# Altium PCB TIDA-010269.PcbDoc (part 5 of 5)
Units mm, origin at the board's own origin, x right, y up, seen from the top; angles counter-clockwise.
Board outline 87.61 x 53.51 mm, 8 copper layers (Top Layer, GND1, Signal 1, Power 1, Power 2, Signal 2, Layer 1, Bottom Layer), stack 1.645 mm thick; 482 components, 227 nets, 1562 pads, 953 vias.
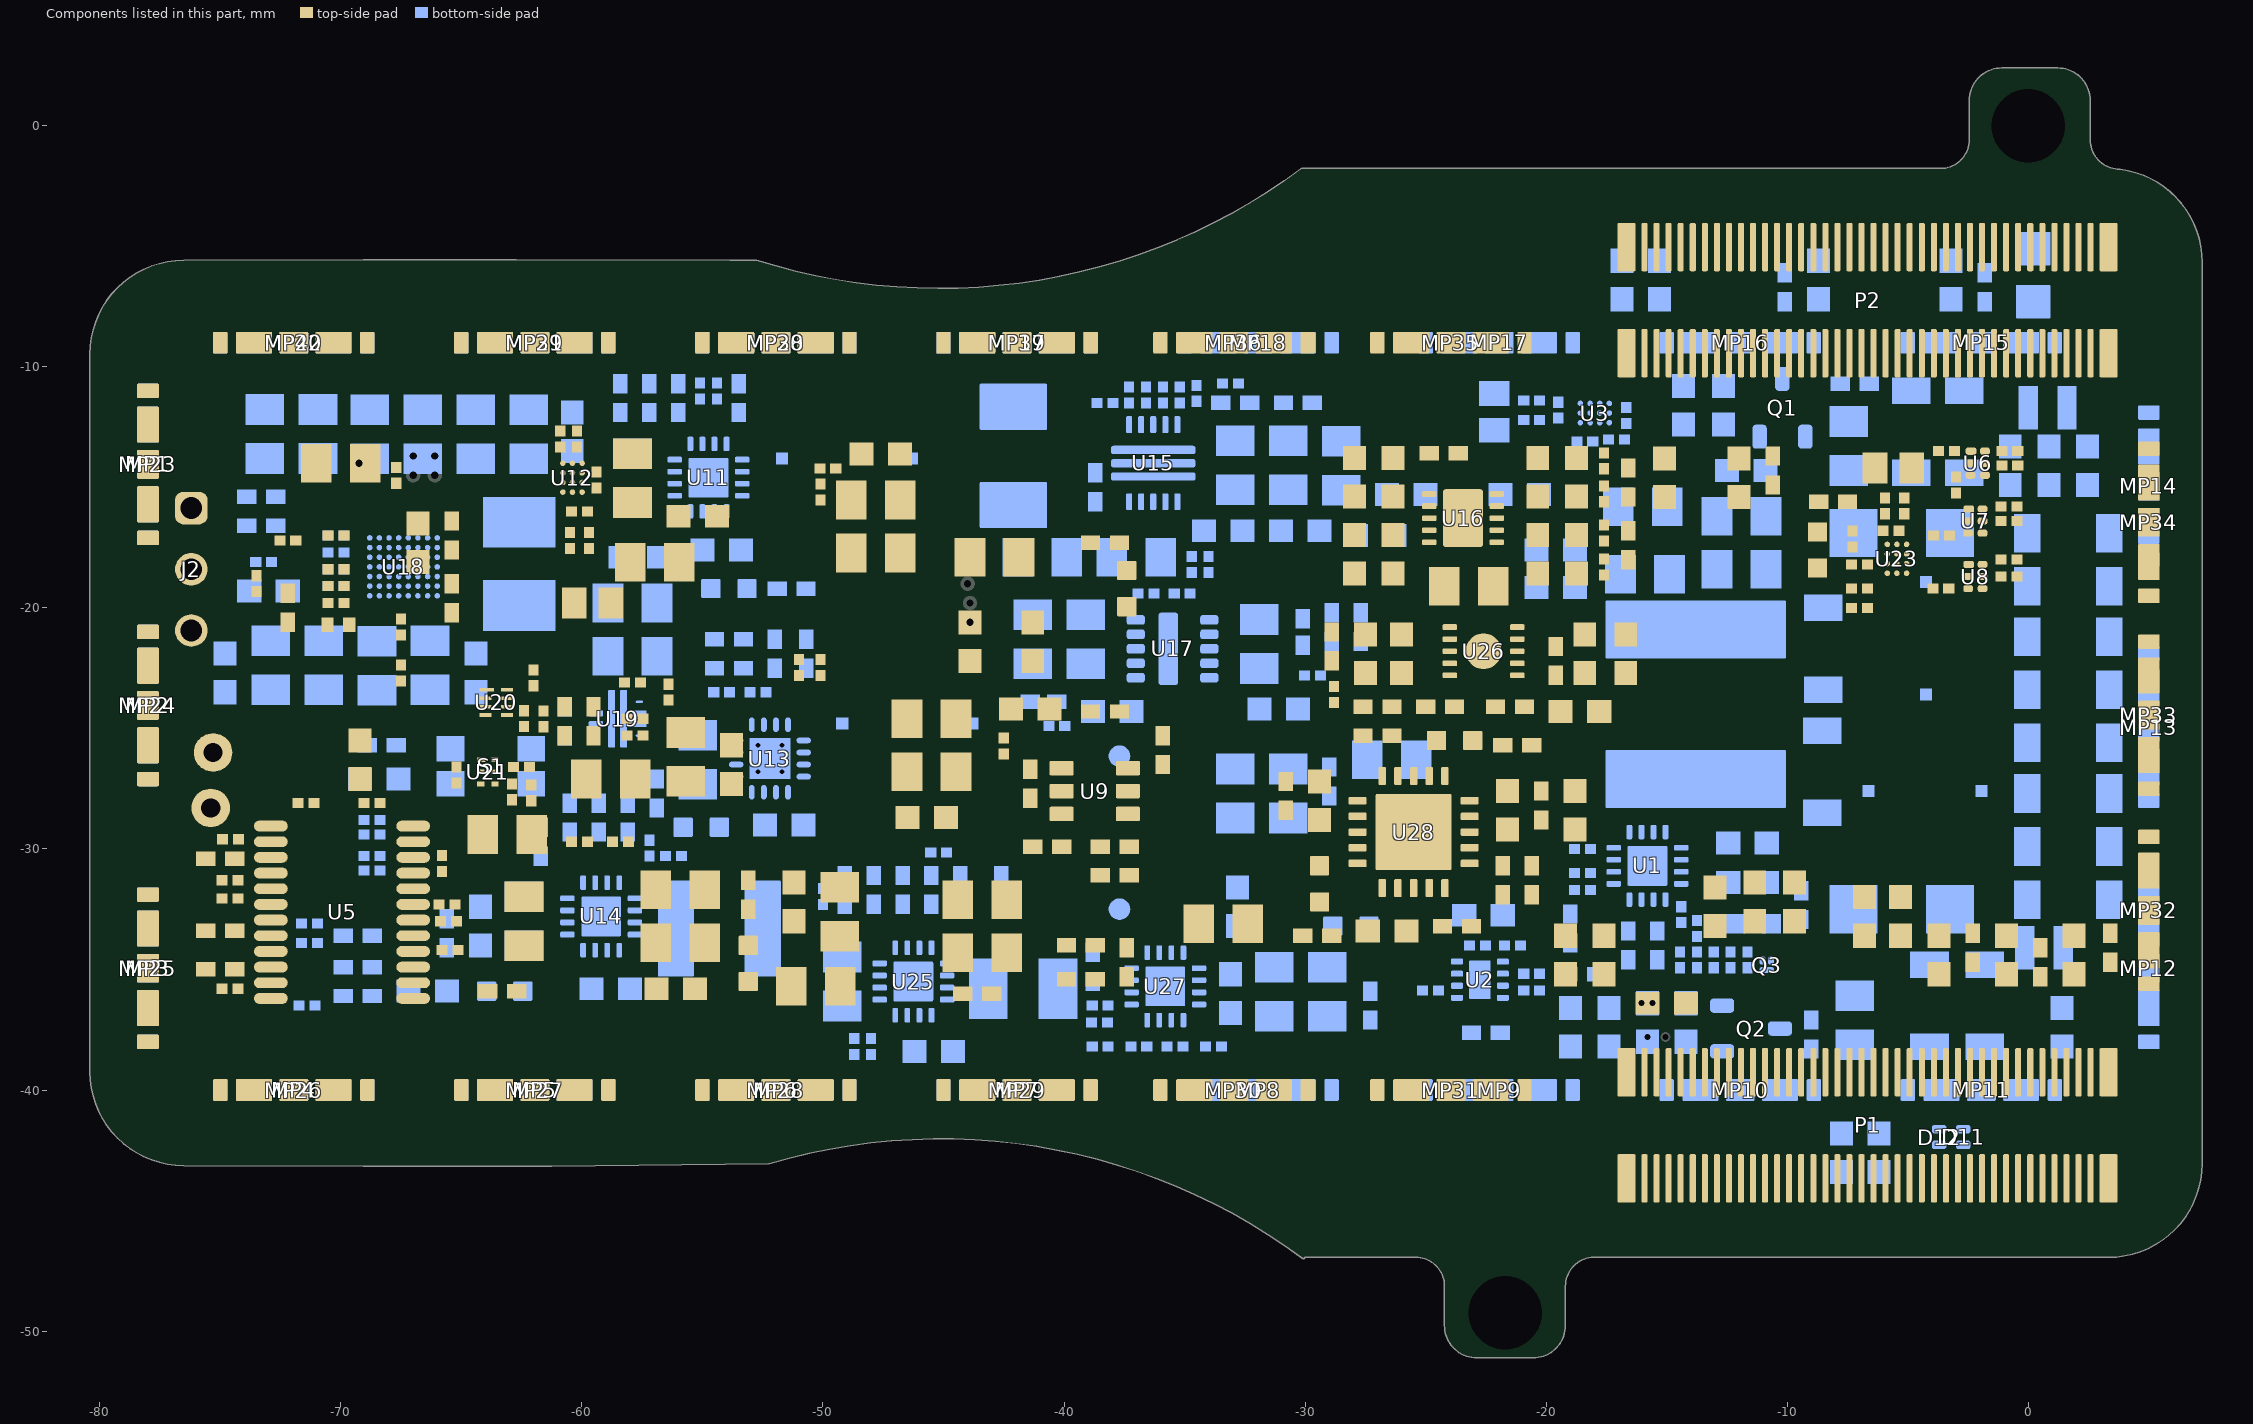
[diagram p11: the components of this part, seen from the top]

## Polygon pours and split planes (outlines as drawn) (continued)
NetC102_1 on Top Layer "TOP_LAYER_NETC102_1_P331" (solid, remove dead copper, pour order 331): -13.475,-32.1 -12.525,-32.1 -12.525,-31.025 -12.4,-30.9 -12.4,-30.5 -12.5,-30.4 -13.35,-30.4 -13.475,-30.525
GND on Top Layer "TOP_LAYER_GND_P292" (solid, remove dead copper, pour order 292): -26.3,-32.925 -26.175,-32.8 -24,-32.8 -23.9,-32.9 -23.9,-33.9 -24.1,-34.1 -26.075,-34.1 -26.3,-33.875
no net on Top Layer "TOP_LAYER_NONET_P284" (solid, remove dead copper, pour order 284): -10.9,-14.5 -9.7,-14.5
MHV on Top Layer "TOP_LAYER_MHV_P282" (solid, remove dead copper, pour order 282): -14.1,-37.3 -14.1,-38 -14.2,-38.1 -16.2,-38.1 -16.31,-38.21 -16.31,-44.63 -16.344,-44.664 -16.997,-44.664 -17.046,-44.615 -17.046,-37.446 -16.8,-37.2 -14.2,-37.2
GND on Top Layer "TOP_LAYER_GND_P276" (solid, remove dead copper, pour order 276): -13.046,-38.314 -13.046,-44.614 -12.996,-44.664 -12.325,-44.664 -12.296,-44.635 -12.296,-38.314 -12.346,-38.264 -12.996,-38.264
GND on Top Layer "TOP_LAYER_GND_P275" (solid, remove dead copper, pour order 275): -15.046,-38.314 -14.996,-38.264 -14.421,-38.264 -14.406,-38.279 -14.31,-38.279 -14.31,-44.599 -14.296,-44.614 -14.346,-44.664 -14.996,-44.664 -15.046,-44.614
GND on Top Layer "TOP_LAYER_GND_P274" (solid, remove dead copper, pour order 274): -9.346,-38.264 -9.296,-38.314 -9.3,-38.318 -9.3,-41 -9.4,-41.1 -10.4,-41.1 -10.5,-41 -10.496,-40.996 -10.496,-38.264 -10.496,-40.996 -10.496,-38.264
GND on Top Layer "TOP_LAYER_GND_P273" (solid, remove dead copper, pour order 273): -10.546,-44.635 -10.516,-44.664 -9.421,-44.664 -9.296,-44.539 -9.296,-42.504 -9.3,-42.5 -9.3,-42.3 -9.5,-42.1 -10.4,-42.1 -10.546,-42.246
PHV on Top Layer "TOP_LAYER_PHV_P267" (solid, remove dead copper, pour order 267): -16.997,-4.038 -16.344,-4.038 -16.296,-4.086 -16.296,-10.504 -16.2,-10.6 -15.1,-10.6 -15,-10.7 -15,-11.8 -15.1,-11.9 -16.3,-11.9 -16.9,-11.9 -17.046,-11.754 -17.046,-4.086
NetC112_1 on Top Layer "TOP_LAYER_NETC112_1_P189" (solid, remove dead copper, pour order 189): 20 vertices, not listed, extent -22.8,-18 -16.3,-16.34
NetC169_1 on Top Layer "TOP_LAYER_NETC169_1_P256" (solid, remove dead copper, pour order 256): -18.875,-20.6 -14.2,-20.6 -14.2,-24.1 -15.9,-24.1 -15.9,-21.6 -18.875,-21.6
NetC169_1 on Top Layer "TOP_LAYER_NETC169_1_P248" (solid, remove dead copper, pour order 248): -21.45,-21.9 -20,-21.9 -19.9,-22 -19.3,-22 -19.3,-21.6 -14.6,-21.6 -14.625,-21.575 -14.625,-14.9 -15.575,-14.9 -15.7,-15.025 -15.7,-20.6 -21.37,-20.6 -21.485,-20.716 -21.485,-21.905
NetC112_1 on Top Layer "TOP_LAYER_NETC112_1_P245" (solid, remove dead copper, pour order 245): -18.725,-34.1 -20,-34.1 -20,-33.1 -21,-33.1 -21,-32.5 -18.7,-32.5 -18.7,-34.075
NetC63_1 on Top Layer "TOP_LAYER_NETC63_1_P238" (solid, remove dead copper, pour order 238): -47.435,-14.725 -47.41,-14.7 -45.8,-14.7 -45.8,-22.9 -45.9,-23 -47.5,-23 -47.5,-14.79 -47.435,-14.725
VDD_FPGA on Top Layer "TOP_LAYER_VDD_FPGA_P235" (solid, remove dead copper, pour order 235): 26 vertices, not listed, extent -60.317,-29.3 -48.2,-17.3
VDD_FPGA on Top Layer "TOP_LAYER_VDD_FPGA_P233" (solid, remove dead copper, pour order 233): -60.8,-20.4 -59.8,-20.4 -59.7,-20.3 -59.7,-18.887 -57.413,-18.887 -57.4,-18.9 -57.4,-17.3 -58.6,-17.3 -58.7,-17.4 -58.7,-18 -60.8,-18
NetC135_1 on Top Layer "TOP_LAYER_NETC135_1_P221" (solid, remove dead copper, pour order 221): 18 vertices, not listed, extent -67.4,-24 -58,-13.2
GND on Top Layer "TOP_LAYER_GND_P212" (solid, remove dead copper, pour order 212): 18 vertices, not listed, extent -21.5,-24.775 -16.225,-22.2
NetC172_1 on Top Layer "TOP_LAYER_NETC172_1_P204" (solid, remove dead copper, pour order 204): -43.019,-31.3 -41.749,-31.3 -41.749,-33.872 -41.721,-33.9 -41,-33.9 -41,-36.3 -43.4,-36.3 -43.4,-35.7 -43,-35.7 -43.019,-35.681
NetC81_1 on Top Layer "TOP_LAYER_NETC81_1_P124" (solid, remove dead copper, pour order 124): -55.619,-30.9 -53.725,-30.9 -53.675,-36.3 -54.5,-36.3 -54.525,-36.275 -55.8,-36.275 -55.8,-35.325 -55.619,-35.325
NetC125_1 on Top Layer "TOP_LAYER_NETC125_1_P170" (solid, remove dead copper, pour order 170): -70.381,-14.8 -74,-14.8 -74,-20.1 -72.7,-20.1 -72.7,-22.4 -75.2,-22.4 -75.2,-13.2 -70.381,-13.2 -70.381,-13.433
VDD_FPGA on Top Layer "TOP_LAYER_VDD_FPGA_P201" (solid, remove dead copper, pour order 201): -62.719,-28.6 -60.451,-28.6 -60.451,-26.3 -59.181,-26.3 -59.181,-29.3 -61.449,-29.3 -61.449,-30.2 -62.719,-30.2
NetC102_1 on Top Layer "TOP_LAYER_NETC102_1_P193" (solid, remove dead copper, pour order 193): 17 vertices, not listed, extent -22.3,-15.88 -16.3,-14.88
NetC113_1 on Top Layer "TOP_LAYER_NETC113_1_P181" (solid, remove dead copper, pour order 181): -28.425,-16.48 -25.875,-16.48 -25.875,-17.16 -24.601,-17.16 -24.601,-17.48 -25.875,-17.48 -28.425,-17.48
GND on Top Layer "TOP_LAYER_GND_P180" (solid, remove dead copper, pour order 180): -25.875,-14.28 -29.7,-14.28 -29.7,-12.4 -27.3,-12.4 -27.3,-13.3 -27.28,-13.28 -25.875,-13.28
GND on Top Layer "TOP_LAYER_GND_P046" (solid, remove dead copper, pour order 46): 20 vertices, not listed, extent -51.675,-36.3 -43.781,-30.7
NetC75_1 on Top Layer "TOP_LAYER_NETC75_1_P173" (solid, remove dead copper, pour order 173): -63.481,-28.6 -63.481,-33 -61.6,-33 -61.6,-36.2 -63.1,-36.2 -63.1,-35.1 -63.6,-34.6 -64.7,-34.6 -64.7,-28.6
GND on Top Layer "TOP_LAYER_GND_P061" (solid, remove dead copper, pour order 61): -53.3,-16.7 -54.875,-16.7 -54.9,-16.675 -54.9,-15.4 -55.6,-15.4 -55.6,-14.616 -59.61,-14.616 -59.61,-14.37 -59.61,-12.9 -53.3,-12.9
NetC195_1 on Top Layer "TOP_LAYER_NETC195_1_P048" (solid, remove dead copper, pour order 48): -28.185,-29.44 -27.4,-29.44 -27.4,-27.4 -26.645,-27.337 -26.645,-26 -31.8,-26 -31.8,-27.673 -31.7,-27.673 -28.322,-27.673 -28.15,-27.845 -28.185,-27.88
NetC206_1 on Top Layer "TOP_LAYER_NETC206_1_P165" (solid, remove dead copper, pour order 165): -39.1,-35.1 -39.1,-35.7 -37.1,-35.7 -37.1,-34.8 -39.1,-34.8
NetC122_2 on Top Layer "TOP_LAYER_NETC122_2_P135" (solid, remove dead copper, pour order 135): -35.975,-20.2 -34.25,-20.2 -34.2,-20.25 -34.2,-22.05 -34.2,-21.8 -30.5,-21.8 -30.5,-21.15 -29.8,-21.15 -29.8,-21.95 -29.8,-23 -36.075,-23 -36.075,-20.3
VDDM_LV5 on Top Layer "TOP_LAYER_VDDM_LV5_P160" (solid, remove dead copper, pour order 160): -19.675,-34.7 -17.3,-34.7 -17.3,-44.9 -14.046,-44.9 -14.046,-42.714 -13.296,-42.714 -13.2,-42.81 -13.2,-45.8 -18.3,-45.8 -18.3,-36 -19.7,-36 -19.675,-35.975
VDDP_LV5 on Top Layer "TOP_LAYER_VDDP_LV5_P158" (solid, remove dead copper, pour order 158): -10.8,-32.7 -10.8,-37.9 -10.8,-44.6 -12,-44.6 -12,-35.3 -13.6,-35.3 -13.6,-32.7
VCC_INT_1V on Top Layer "TOP_LAYER_VCC_INT_1V_P150" (solid, remove dead copper, pour order 150): -2.6,-34.3 -2,-34.3 -2,-36 -4.796,-36 -4.796,-44.614 -4.846,-44.664 -4.86,-44.649 -5.531,-44.649 -5.531,-34.7 -4.175,-34.7 -2.6,-34.7
VCC_AUX_1V8 on Top Layer "TOP_LAYER_VCC_AUX_1V8_P148" (solid, remove dead copper, pour order 148): 18 vertices, not listed, extent -2.046,-40.264 0.8,-34.7
NetC169_1 on Top Layer "TOP_LAYER_NETC169_1_P144" (solid, remove dead copper, pour order 144): -22.835,-18.3 -21,-18.3 -21,-20 -20,-20 -20,-21.8 -20.1,-21.9 -21.45,-21.9 -21.45,-20.15 -21.565,-20.035 -21.565,-19.9 -22.835,-19.9
NetC172_1 on Top Layer "TOP_LAYER_NETC172_1_P143" (solid, remove dead copper, pour order 143): -24.867,-18.3 -24.9,-18.333 -24.9,-21.4 -23.772,-21.4 -23.751,-21.421 -23.597,-21.267 -23.597,-18.3
GND on Top Layer "TOP_LAYER_GND_P142" (solid, remove dead copper, pour order 142): 19 vertices, not listed, extent -25.1,-17.48 -18.275,-13.1
VBUS on Top Layer "TOP_LAYER_VBUS_P140" (solid, remove dead copper, pour order 140): -44.535,-17.1 -44.535,-20.94 -44.375,-21.1 -43.425,-21.1 -43.425,-18.86 -43.265,-18.7 -43.265,-17.1
NetC120_1 on Top Layer "TOP_LAYER_NETC120_1_P139" (solid, remove dead copper, pour order 139): -44.375,-21.7 -40.825,-21.7 -40.825,-23 -44.3,-23 -44.4,-22.9 -44.375,-22.875
NetC72_1 on Top Layer "TOP_LAYER_NETC72_1_P138" (solid, remove dead copper, pour order 138): -58.419,-26.3 -58.419,-27.9 -56.565,-27.9 -56.465,-27.8 -53.325,-27.8 -53.325,-26.8 -54.9,-26.8 -54.9,-26.565 -56.5,-26.565 -56.505,-26.57 -57.149,-26.57 -57.149,-26.3
GND on Top Layer "TOP_LAYER_GND_P127" (solid, remove dead copper, pour order 127): -40.749,-27.5 -40.6,-27.351 -39.6,-27.351 -39.6,-27.87 -39.63,-27.9 -41.1,-27.9 -41.1,-28.3 -42.3,-28.3 -42.3,-27.5 -41.1,-27.5
GND on Top Layer "TOP_LAYER_GND_P126" (solid, remove dead copper, pour order 126): -41.1,-27.5 -41.1,-29.6 -40.9,-29.6 -40.9,-30.4 -42.2,-30.4 -42.2,-31.5 -44.6,-31.5 -44.6,-30.7 -43,-30.7 -43,-27.5
NetC174_1 on Top Layer "TOP_LAYER_NETC174_1_P123" (solid, remove dead copper, pour order 123): 23 vertices, not listed, extent -53.4,-36.8 -48.5,-30.9
GND on Top Layer "TOP_LAYER_GND_P122" (solid, remove dead copper, pour order 122): -57.651,-30.9 -56.381,-30.9 -56.381,-34.7 -56.599,-34.7 -56.599,-36.274 -56.6,-36.275 -57.6,-36.275 -57.6,-33.696 -57.651,-33.645 -57.706,-33.7 -60,-33.7 -60,-32 -57.673,-32 -57.651,-31.978
GND on Top Layer "TOP_LAYER_GND_P075" (solid, remove dead copper, pour order 75): -62.87,-24.7 -59.219,-24.7 -59.219,-26.16 -61.76,-26.16 -61.75,-26.17 -61.75,-27.57 -62.87,-27.57 -62.87,-26.5
GND on Top Layer "TOP_LAYER_GND_P101" (solid, remove dead copper, pour order 101): 19 vertices, not listed, extent -29.01,-25.6 -25.721,-22.2
NetC109_1 on Top Layer "TOP_LAYER_NETC109_1_P099" (solid, remove dead copper, pour order 99): -28.425,-14.88 -28.405,-14.9 -24.6,-14.9 -24.6,-15.899 -24.601,-15.9 -24.621,-15.88 -28.425,-15.88
GND on Top Layer "TOP_LAYER_GND_P097" (solid, remove dead copper, pour order 97): -47.151,-23.8 -45.881,-23.8 -45.881,-27.981 -46,-28.1 -46,-29.175 -47,-29.175 -47,-27.751 -47.151,-27.6
GND on Top Layer "TOP_LAYER_GND_P095" (solid, remove dead copper, pour order 95): -56.67,-25.803 -54.403,-25.803 -54.275,-25.931 -54.275,-26.2 -53.325,-26.2 -53,-26.2 -53,-27.1 -51.3,-27.1 -51.3,-25 -54,-25 -54,-23.6 -56.67,-23.6
NetC63_1 on Top Layer "TOP_LAYER_NETC63_1_P063" (solid, remove dead copper, pour order 63): -47.3,-13.15 -47.3,-14.59 -47.435,-14.725 -47.435,-18.525 -45.9,-18.525 -45.9,-14.925 -45.9,-13.15
NetC172_1 on Top Layer "TOP_LAYER_NETC172_1_P032" (solid, remove dead copper, pour order 32): -29.2,-20.6 -24.38,-20.6 -24.285,-20.695 -24.27,-20.68 -23.75,-20.68 -23.75,-21.42 -23.751,-21.421 -25.525,-21.421 -25.525,-21.6 -27.975,-21.6 -27.975,-21.41 -27.985,-21.4 -29.2,-21.4
NetC190_1 on Top Layer "TOP_LAYER_NETC190_1_P031" (solid, remove dead copper, pour order 31): 18 vertices, not listed, extent -24.305,-29.455 -18.325,-26.3
NetC79_1 on Power 2 "POWER_2_NETC79_1_P365" (solid, remove dead copper, pour order 365): -3.25,-31.3 -6.3,-31.3 -6.5,-31.1 -6.5,-27.75 -6.75,-27.5 -54.604,-27.5 -56,-26.105 -56,-22 -54.5,-20.5 -2.9,-20.5 -2.4,-21 -2.4,-30.45
VCC_AUX_1V8 on Power 2 "POWER_2_VCC_AUX_1V8_P304" (solid, remove dead copper, pour order 304): -58,-22.346 -55.654,-20 -16,-20 -16,-10 -18,-8 -78,-8 -80,-10 -80,-39.653 -77.653,-42 -58,-42
VCC_AUX_1V8 on Power 2 "POWER_2_VCC_AUX_1V8_P310" (solid, remove dead copper, pour order 310): -3,-35.5 -0.1,-35.5 0.4,-35 0.4,-21 -0.6,-20 -19,-20 -19,-8.844 -18.156,-8 4,-8 6,-10 6,-42 4,-44 -3.1,-44 -3.1,-35.6
NetC81_1 on Power 2 "POWER_2_NETC81_1_P309" (solid, remove dead copper, pour order 309): -10.05,-27.9 -5.95,-32 -0.5,-32 -0.2,-32.3 -0.2,-34.4 -1,-35.2 -54.678,-35.2 -56,-33.878 -56,-29 -54.9,-27.9
VCC_AUX_1V8 on Power 2 "POWER_2_VCC_AUX_1V8_P305" (solid, remove dead copper, pour order 305): -29,-43 -28,-44 -2,-44 -1,-43 -1,-36 -1.5,-35.5 -27.5,-35.5 -29,-37
VBUS_HV on Power 1 "POWER_1_VBUS_HV_P316" (solid, remove dead copper, pour order 316): -23.6,-14.1 -23.6,-18.4 -22.3,-19.7 -15.7,-19.7 -15,-19 -15,-12.9 -15.9,-12 -23.1,-12 -23.6,-12.5
VCCO_2V5 on Power 1 "POWER_1_VCCO_2V5_P401" (solid, remove dead copper, pour order 401): 18 vertices, not listed, extent -69.95,-41 -19.8,-26
1V8_DVDD on Power 1 "POWER_1_1V8_DVDD_P394" (solid, remove dead copper, pour order 394): 22 vertices, not listed, extent -17.927,-44.65 6,-13
NetC125_1 on Power 1 "POWER_1_NETC125_1_P324" (solid, remove dead copper, pour order 324): 17 vertices, not listed, extent -77,-25 1.219,-7.35
VBUS on Power 1 "POWER_1_VBUS_P318" (solid, remove dead copper, pour order 318): 22 vertices, not listed, extent -60,-37 -24,-12
VDD on Power 1 "POWER_1_VDD_P325" (solid, remove dead copper, pour order 325): -67.91,-27.85 -67.5,-28.223 -67.5,-36.4 -67.85,-36.75 -71.5,-36.75 -72.55,-35.7 -72.55,-28.85 -71.55,-27.85
NetC63_1 on Power 1 "POWER_1_NETC63_1_P323" (solid, remove dead copper, pour order 323): -27,-31 -26.3,-31.7 -2.684,-31.7 -2,-31.016 -2,-20.8 -2.4,-20.4 -25.9,-20.4 -27,-21.5
NetC63_1 on Power 1 "POWER_1_NETC63_1_P322" (solid, remove dead copper, pour order 322): -48,-23.8 -47.8,-24 -18.4,-24 -3.8,-24 -2,-22.2 -2,-20.8 -2.4,-20.4 -41.3,-20.4 -42.2,-21.3 -47.8,-21.3 -48,-21.5
VBUS on Power 1 "POWER_1_VBUS_P321" (solid, remove dead copper, pour order 321): -43,-20.8 -43.2,-21 -44.8,-21 -45,-20.8 -45,-18.8 -45.819,-17.981 -45.819,-13 -42.3,-13 -42.3,-18.1 -43,-18.8
GND on Signal 2 "SIGNAL_2_GND_P431" (solid, remove dead copper, pour order 431): -75.707,-46.943 -80.4,-42.25 -80.4,-3.15 -79,-1.75 4.95,-1.75 7.206,-4.006 7.206,-46.144 6.407,-46.943 3.574,-46.943
AVDD_1P2 on Signal 2 "SIGNAL_2_AVDD_1P2_P422" (solid, remove dead copper, pour order 422): -6.25,-5.8 -5.9,-6.15 -5.9,-11.05 -6.15,-11.3 -8.6,-11.3 -8.95,-11.65 -8.95,-13.1 -9.75,-13.9 -12.2,-13.9 -12.7,-13.4 -12.7,-6.05 -12.45,-5.8
VBUS on Signal 2 "SIGNAL_2_VBUS_P330" (solid, remove dead copper, pour order 330): -19.202,-11.502 -19.202,-12.998 -18.9,-13.3 -17.2,-13.3 -17.2,-16.8 -16.7,-17.3 -16.7,-24.5 -16.55,-24.65 -15.5,-24.65 -15.3,-24.45 -15.3,-11 -15.5,-10.8 -18.5,-10.8
NetC102_1 on Signal 2 "SIGNAL_2_NETC102_1_P423" (solid, remove dead copper, pour order 423): 26 vertices, not listed, extent -22.5,-30.9 -11.375,-7.85
USB_5V on Signal 2 "SIGNAL_2_USB_5V_P419" (solid, remove dead copper, pour order 419): -3.5,-5.8 -5.45,-5.8 -5.7,-6.05 -5.7,-11.45 -6.1,-11.85 -7.1,-11.85 -7.6,-12.35 -7.6,-14.55 -7.15,-15 -6,-15 -3.95,-15 -3.2,-14.25 -3.2,-6.1
NetC112_1 on Signal 2 "SIGNAL_2_NETC112_1_P328" (solid, remove dead copper, pour order 328): -24.3,-17.2 -17.7,-17.2 -17,-17.9 -17,-27 -18,-28 -18,-33.2 -18.4,-33.6 -23.9,-33.6 -25,-32.5 -25,-17.9
GND on Signal 1 "SIGNAL_1_GND_P430" (solid, remove dead copper, pour order 430): -3.297,-1.723 -77.623,-1.723 -80.5,-4.6 -80.374,-4.726 -80.374,-44.876 -78.15,-47.1 -77.993,-46.943 6.507,-46.943 7.25,-46.2 7.25,-2 7.45,-1.8 7.424,-1.774 -3.644,-1.774
VBUS on Signal 1 "SIGNAL_1_VBUS_P369" (solid, remove dead copper, pour order 369): -16.7,-21.8 -16.7,-24.4 -16.55,-24.55 -1.1,-24.55 -0.5,-23.95 -0.5,-14.1 -0.8,-13.8 -2.45,-13.8 -2.75,-14.1 -2.75,-16.9 -6.85,-21 -15.9,-21
VCCO_2V5 on Signal 1 "SIGNAL_1_VCCO_2V5_P402" (solid, remove dead copper, pour order 402): -8.3,-37.8 -8,-38.1 -8,-41.6 -8.15,-41.75 -22.25,-41.75 -23.1,-40.9 -23.1,-38.25 -22.65,-37.8 -22.25,-37.8
GND on GND1 "GND1_GND_P383" (solid, remove dead copper, pour order 383): 4.325,-46.81 3.936,-47.2 -78.25,-47.2 -80.3,-45.15 -80.3,-3.8 -78.25,-1.75 -78.1,-1.9 4.15,-1.9 7.4,-5.15 7.074,-5.476 7.074,-45.176 5.44,-46.81
GND on Layer 1 "LAYER_1_GND_P467" (solid, remove dead copper, pour order 467): -30.188,-1.796 4.896,-1.796 7.074,-3.974 7.074,-44.063 4.271,-46.866 -76.034,-46.866 -80.33,-42.57 -80.33,-6.33 -79,-5 -36.4,-5 -33.185,-1.785 -30.161,-1.785
HVGND on Layer 1 "LAYER_1_HVGND_P466" (solid, remove dead copper, pour order 466): -28.2,-8 -25.784,-5.584 1.784,-5.584 3.981,-7.781 3.981,-41.919 2.488,-43.412 -25.788,-43.412 -28.2,-41

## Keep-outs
Keep-Out Layer:
  circle w0.003: c-75.898,-44.595 r1.331
  circle w0.003: c-75.898,-4.107 r1.331

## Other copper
Signal 2:
  text ".layer_name" at -77.79,-98.031 h1.85
Bottom Layer:
  pour cut-out: -15.2,-28.7 -15,-28.5

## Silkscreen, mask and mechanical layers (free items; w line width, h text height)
Top Overlay:
  text "TIDA-010269" at -30,-5 h1.02
  text "REV 00" at -29.9,-6.3 h1.02
  text "C" at -17.1,-49 h1.02
Bottom Overlay:
  text ".Layer_Name" at -80.711,-98.21 h1.52
Top Paste:
  text ".Layer_Name" at -80.711,-98.21 h1.52
Bottom Paste:
  text ".Layer_Name" at -80.711,-98.21 h1.52
Top Solder:
  text ".Layer_Name" at -80.711,-98.21 h1.52
  text ".Layer_Name" at -80.711,-98.21 h1.52
Bottom Solder:
  text ".Layer_Name" at -80.711,-98.21 h1.52
Drill Guide:
  text ".Layer_Name" at -80.711,-98.21 h1.52
M1 Board Outline:
  lines w0.152: -80.33,-27 -80.33,-9.471 cw(c-76.52,-9.471) -76.52,-5.661 -69.07,-5.628 -62.72,-5.628 -53.873,-5.649 -52.783,-5.649 ccw(c-45.171,18.387) -30.143,-1.857 ; -80.33,-19.634 -80.33,-39.246 ccw(c-76.52,-39.246) -76.52,-43.056 -69.07,-43.085 -61.266,-43.085 ; -61.45,-43.085 -52.256,-43.085 ; -52.574,-43.082 cw(c-45.102,-67.162) -30.074,-46.917 ; -30.134,-1.851 -3.644,-1.851 ccw(c-3.644,-0.581) -2.374,-0.581 -2.374,1.05 cw(c-1.104,1.05) -1.104,2.32 1.219,2.32 cw(c1.219,1.05) 2.489,1.05 2.489,-0.581 ccw(c3.79,-0.581) 3.804,-1.882 cw(c3.32,-5.661) 7.13,-5.661 7.13,-43.056 cw(c3.32,-43.056) 3.32,-46.866 -17.922,-46.866 ccw(c-18.006,-48.136) -19.279,-48.136 -19.279,-49.767 cw(c-20.549,-49.767) -20.549,-51.037 -22.872,-51.037 cw(c-22.872,-49.767) -24.142,-49.767 -24.142,-48.136 ccw(c-25.412,-48.136) -25.412,-46.866 -30.127,-46.866 -30.131,-46.87
M2 Board Dimensions:
  rectangle: -95.367,-83.39 -92.192,-80.215
  rectangle: -92.192,-86.565 -82.667,-83.39
  lines w0.178: -95.367,-83.39 -69.967,-83.39 ; -92.192,-86.565 -92.192,-80.215 ; -89.017,-86.565 -89.017,-80.215 ; -82.667,-86.565 -82.667,-80.215 ; -76.317,-86.565 -76.317,-80.215 ; -95.367,-86.565 -69.967,-86.565 -69.967,-80.215 -95.367,-80.215 -95.367,-86.565
M3 3D STEP Top:
  text ".Layer_Name" at -80.711,-98.21 h1.52
M4 3D STEP Bottom:
  text ".Layer_Name" at -80.711,-98.21 h1.52
M5 Assembly Top:
  lines w0.254: -102.784,-100.031 64.856,-100.031 ; -102.784,-94.866 64.907,-94.866 ; -102.784,-89.702 -102.784,-105.196 -1.057,-105.196 64.907,-105.196 64.907,-89.702 -102.771,-89.702 -102.771,-105.196 -62.753,-105.196 ; -40.173,-105.196 -40.173,-89.702 ; -7.991,-94.866 -7.991,-89.702 ; 13.345,-94.866 13.345,-89.702 ; 29.144,-105.361 29.144,-100.209
  text "COMPONENTS MARKED 'DNP' SHOULD NOT BE POPULATED." at -66.068,-84.495 h1.52
  text "ASSEMBLY VARIANT:" at -66.081,-87.428 h1.52
  text ".VariantName" at -39.766,-87.428 h1.52
  text "PCB VIEWED FROM TOP SIDE" at -101.171,-93.059 h1.52
  text "BOARD #:" at -38.268,-93.059 h1.52
  text ".PRJ_Number" at -24.412,-93.059 h1.52
  text "REV:" at -2.962,-93.059 h1.52
  text ".PCB_Rev" at 4.442,-93.059 h1.52
  text "SVN REV:" at 18.324,-93.059 h1.52
  text ".VersionControl_RevNumber" at 31.176,-93.059 h1.52
  text ".layer_name" at -80.635,-97.93 h1.85
  text "TID #:" at -38.268,-98.223 h1.52
  text ".TID" at -24.412,-98.223 h1.52
  text "PLOT NAME =" at -101.171,-103.439 h1.52
  text ".plot_File_Name" at -80.711,-103.439 h1.52
  text "GENERATED    :" at -38.217,-103.439 h1.52
  text ".Print_Date" at -16.132,-103.439 h1.52
  text ".Print_Time" at 2.385,-103.439 h1.52
  text "TEXAS INSTRUMENTS" at 34.503,-103.439 h1.52
M6 Assembly Bottom:
  lines w0.254: -102.796,-94.879 64.894,-94.879 ; -102.746,-100.044 64.894,-100.044 ; -67.033,-105.373 -67.033,-100.221 ; -51.234,-94.879 -51.234,-89.714 ; -29.898,-94.879 -29.898,-89.714 ; 2.283,-105.208 2.283,-89.714 ; 24.864,-105.208 64.882,-105.208 64.882,-89.714 -102.796,-89.714 -102.796,-105.208 -36.833,-105.208 64.894,-105.208 64.894,-89.714
  text "R" at -24.694,-6.284 h0.51
  text "R" at -47.158,-7.099 h0.51
  text "Q" at -25.034,-24.153 h0.51
  text "Q" at -47.844,-27.419 h0.51
  text "COMPONENTS MARKED 'DNP' SHOULD NOT BE POPULATED." at 59.624,-84.482 h1.52
  text ".VariantName" at 33.106,-87.428 h1.52
  text "ASSEMBLY VARIANT:" at 59.497,-87.428 h1.52
  text ".VersionControl_RevNumber" at -69.065,-93.071 h1.52
  text "SVN REV:" at -56.213,-93.071 h1.52
  text ".PCB_Rev" at -42.332,-93.071 h1.52
  text "REV:" at -34.928,-93.071 h1.52
  text ".PRJ_Number" at -13.477,-93.071 h1.52
  text "BOARD #:" at 0.378,-93.071 h1.52
  text "PCB VIEWED FROM BOTTOM SIDE" at 63.282,-93.071 h1.52
  text ".TID" at -13.477,-98.236 h1.52
  text "TID #:" at 0.378,-98.236 h1.52
  text ".layer_name" at 50.708,-98.361 h1.85
  text "TEXAS INSTRUMENTS" at -72.393,-103.451 h1.52
  text ".Print_Time" at -40.274,-103.451 h1.52
  text ".Print_Date" at -21.758,-103.451 h1.52
  text "GENERATED    :" at 0.328,-103.451 h1.52
  text ".plot_File_Name" at 42.822,-103.451 h1.52
  text "PLOT NAME =" at 63.282,-103.451 h1.52
M9 Title Sheet:
  drawing of 57 lines, arcs and shapes, not listed
  text "1" at -76.575,127.722 h1.78
  text "2" at -13.185,127.722 h1.78
  text "3" at 50.044,127.722 h1.78
  text "4" at 113.714,127.722 h1.78
  text "5" at 177.188,127.722 h1.78
  text "6" at 240.815,127.722 h1.78
  text "A" at -105.946,98.69 h1.78
  text "A" at 269.974,98.69 h1.78
  text "B" at -105.946,38.238 h1.78
  text "B" at 269.974,38.238 h1.78
  text "C" at -105.946,-22.087 h1.78
  text "C" at 269.974,-22.087 h1.78
  text "PROJECT TITLE:" at 192.758,-69.356 h1.14
  text ".PRJ_Title" at 194.028,-72.743 h1.78
  text "DESIGNED FOR:" at 192.758,-77.002 h1.14
  text ".PRJ_Customer" at 194.028,-80.558 h1.78
  text "D" at -105.946,-82.285 h1.78
  text "D" at 269.974,-82.285 h1.78
  text "FILE NAME:" at 192.758,-84.622 h1.14
  text ".PCB_File_Name_No_Path" at 194.028,-87.67 h1.78
  text "Texas Instruments (TI) and/or its licensors do not warrant the accuracy or completeness of this specification" at 66.533,-91.78 h1.14
  text "ENGINEER:" at 192.758,-91.988 h1.14
  text "LAYOUT BY:" at 230.985,-91.988 h1.14
  text "or any information contained therein. TI and/or its licensors do not warrant that this design will meet" at 65.39,-94.642 h1.14
  text ".PRJ_Engineer" at 194.028,-95.924 h1.78
  text ".PCB_Layout" at 232.268,-95.924 h1.78
  text "the specifications, will be suitable for your application or fit for any particular purpose, or will operate in" at 65.39,-97.504 h1.14
  text "ALTIUM DESIGNER VERSION:" at 230.985,-99.862 h1.14
  text "an implementation. TI and/or its licensors do not warrant that the design is production worthy. You should" at 65.39,-100.365 h1.14
  text "completely validate and test your design implementation to confirm the system functionality for your application." at 66.533,-103.227 h1.14
  text ".print_Scale" at 194.028,-103.248 h1.78
  text ".Application_BuildNumber" at 232.268,-103.248 h1.78
  text "1" at -76.575,-108.498 h1.78
  text "2" at -13.185,-108.498 h1.78
  text "3" at 50.044,-108.498 h1.78
  text "4" at 113.714,-108.498 h1.78
  text "5" at 177.188,-108.498 h1.78
  text "6" at 240.815,-108.498 h1.78
M10 Fab Notes:
  drawing of 189 lines, arcs and shapes, not listed
  text "DESIGN INFORMATION" at 219.136,85.042 h1.52
  text "MIN. TRACK WIDTH:" at 202.765,81.686 h1.52
  text "4" at 230.609,81.686 h1.52
  text "MIL" at 234.54,81.686 h1.52
  text "4.75" at 227.51,78.671 h1.52
  text "MIN. CLEARANCE:" at 202.765,78.533 h1.52
  text "MIL" at 234.565,78.486 h1.52
  text "MIN. VIA PAD SIZE:" at 202.765,75.381 h1.52
  text "12" at 229.847,75.381 h1.52
  text "MIL" at 234.54,75.381 h1.52
  text "0.05mm (2MIL)" at 220.418,72.081 h1.52
  text "MINIMUM ANNULAR RING" at 194.402,71.872 h1.52
  text "EXTERNAL" at 238.401,71.872 h1.52
  text "PER" at 199.482,69.075 h1.52
  text "IPC-D-275 CLASS 2 LEVEL C" at 205.07,69.075 h1.52
  text "MIL, HOLES" at 242.871,66.523 h1.52
  text "+/-" at 232.903,66.305 h1.52
  text "+/-" at 254.594,66.305 h1.52
  text "REGISTRATION TOLERANCES:" at 194.402,66.278 h1.52
  text "METAL" at 224.876,66.278 h1.52
  text "5" at 239.512,66.278 h1.52
  text "3" at 260.67,66.278 h1.52
  text "MIL" at 263.623,66.278 h1.52
  text "HOLE SIZE TOLERANCE (UNLESS OTHERWISE SPECIFIED):" at 194.402,63.781 h1.52
  text "+/-" at 254.594,63.708 h1.52
  text "3" at 260.67,63.681 h1.52
  text "MIL" at 263.623,63.681 h1.52
  text "MATERIAL:" at 192.503,60.184 h1.52
  text "FR-4 High Tg" at 217.559,56.92 h1.52
  text "FR-4" at 251.276,56.747 h1.52
  text "FR-408" at 203.196,56.602 h1.52
  text "X" at 236.319,56.599 h1.52
  text "OTHER" at 240.992,56.602 h1.52
  text "62 MIL (1.6mm) +/-10%" at 211.327,52.969 h1.52
  text "X" at 208.277,52.907 h1.52
  text "THICKNESS:" at 194.402,52.76 h1.52
  text "OTHER" at 243.963,52.76 h1.52
  text "TOLERANCE:" at 194.402,49.247 h1.52
  text "X" at 215.947,49.247 h1.52
  text "ANSI IPC-6012 TYPE 3 CLASS 2" at 220.469,49.247 h1.52
  text "OTHER +/-" at 220.468,45.585 h1.52
  text "BOW & TWIST:" at 194.402,41.897 h1.52
  text "X" at 215.947,41.897 h1.52
  text "ANSI IPC-6012 TYPE 3 CLASS 2" at 220.469,41.897 h1.52
  text "OTHER +/-" at 220.468,38.171 h1.52
  text "NOTES: (UNLESS OTHERWISE SPECIFIED)" at 51.193,35.903 h1.52
  text "DRILLING:" at 192.503,34.853 h1.52
  text "NC_DRILL FILES" at 237.232,32.181 h1.52
  text "REFERENCE:" at 194.402,32.081 h1.52
  text "X" at 211.096,32.079 h1.52
  text "AS SHOWN" at 215.617,32.081 h1.52
  text "X" at 233.981,32.081 h1.52
  text "1.FABRICATE PER IPC-6012A CLASS 2" at 51.193,31.575 h1.52
  text "OTHER" at 244.802,28.468 h1.52
  text "PTH COPPER THICKNESS:" at 194.394,28.379 h1.52
  text "20-30 um" at 226.582,28.379 h1.52
  text "X" at 223.392,28.289 h1.52
  text "2.LAMINATE MATERIAL: FR4" at 51.193,28.24 h1.52
  text "3.COPPER WEIGHT: SEE STACKUP" at 51.193,24.996 h1.52
  text "BOARD FINISH:" at 192.503,24.63 h1.52
  text "SILKSCREEN:" at 196.446,21.832 h1.52
  text "X" at 220.773,21.832 h1.52
  text "TOP" at 223.745,21.832 h1.52
  text "X" at 233.727,21.832 h1.52
  text "BOTTOM" at 236.724,21.832 h1.52
  text "4.BOARD THICKNESS: 1.6MM +/- 10%" at 51.193,21.61 h1.52
  text "5.NO OF LAYERS: 12 AS PER SUPPLIED ARTWORK" at 51.193,18.552 h1.52
  text "SILKSCREEN COLOR:" at 196.446,17.891 h1.52
  text "X" at 220.748,17.891 h1.52
  text "WHITE" at 223.745,17.891 h1.52
  text "OTHER" at 236.724,17.891 h1.52
  text "6.SURFACE FINISH: ENIG" at 51.193,14.958 h1.52
  text "X" at 224.075,14.247 h1.52
  text "GREEN" at 227.072,14.247 h1.52
  text "OTHER" at 242.77,14.247 h1.52
  text "SOLDER RESIST COLOR:" at 196.446,14.073 h1.52
  text "7.SINGLE ENDED TRACES WITH 7MILS WIDTH IN LAYERS 1,12 AND 4MILS WIDTH IN LAYERS 3,5,8 & 10" at 51.193,11.714 h1.52
  text "X" at 224.075,10.329 h1.52
  text "MATTE" at 227.072,10.329 h1.52
  text "SEMI-GLOSS" at 242.758,10.313 h1.52
  text "TO BE 50 OHM +/- 10% IMPEDANCE CONTROLLED." at 51.193,8.028 h1.52
  text "IMMERSION GOLD (ENIG)" at 219.452,5.941 h1.52
  text "ENEPIG" at 253.426,5.757 h1.52
  text "SURFACE FINISH:" at 192.503,5.732 h1.52
  text "X" at 214.931,5.732 h1.52
  text "8.DIFFERENTIAL TRACES WITH 5MILS WIDTH AND 6MILS SPACING" at 51.193,4.851 h1.52
  text "IMM. TIN/SILVER OR EQUIV" at 200.873,2.244 h1.52
  text "IN LAYERS 1,12 AND 4MILS WIDTH AND 7MILS SPACING" at 51.193,2.181 h1.52
  text "OTHER" at 237.232,2.144 h1.52
  text "IN LAYERS 3,5 & 10 TO BE 100 OHM +/- 10% IMPEDANCE CONTROLLED." at 51.193,-0.997 h1.52
  text "ARRAY/PANEL:" at 192.503,-1.803 h1.52
  text "X" at 214.894,-1.892 h1.52
  text "CUT AND TRIM PER M1 BOARD OUTLINE" at 219.452,-2.011 h1.52
  text "9.SOLDERMASK BOTH SIDES WITH LIQUID PHOTO IMAGEABLE (LPI) PER IPC-SM-840C" at 51.193,-4.682 h1.52
  text "N.C. ROUTE" at 219.452,-5.465 h1.52
  text "V. SCORE" at 241.449,-5.465 h1.52
  text "COLOR:GREEN" at 51.193,-7.851 h1.52
  text "CERTIFICATION:" at 192.503,-8.745 h1.52
  text "MATERIALS AND WORKMANSHIP FOR ALL PCBS" at 210.918,-8.745 h1.52
  text "10.SILKSCREEN: BOTH SIDE WITH PERMANENT NON CONDUCTIVE WHITE EPOXY INK." at 51.193,-11.037 h1.52
  text "TO MEET OR EXCEED THE REQUIREMENTS OF:" at 210.918,-11.134 h1.52
  text "SILKSCREEN MAY BE TRIMMED OFF ANY SOLDERED ENTITY." at 51.193,-14.226 h1.52
  text "X" at 201.711,-14.401 h1.52
  text "ANSI IPC-A-600F CLASS ->" at 204.962,-14.401 h1.52
  text "X" at 246.821,-14.401 h1.52
  text "2" at 249.615,-14.401 h1.52
  text "1" at 241.614,-14.439 h1.52
  text "3" at 258.607,-14.439 h1.52
  text "11.BOW AND TWIST NOT TO EXCEED 0.180MM (0.007\") PER INCH AS MEASURED PER IPC-TM-650." at 51.193,-17.393 h1.52
  text "X" at 222.336,-18.152 h1.52
  text "RoHS" at 225.587,-18.152 h1.52
  text "OTHER" at 241.954,-18.152 h1.52
  text "PER ORDER" at 252.04,-18.152 h1.52
  text "12.SOLDER MASK CLEARANCE IS GIVEN SAME AS PAD SIZE EXCEPT FOR NPTH AND FIDUCIALS." at 51.193,-20.57 h1.52
  text "ALL BOARDS MUST MEET OR EXCEED UL94-V0 REQUIREMENTS." at 193.203,-22.06 h1.52
  text "VENDOR SHALL OVERSIZE THE MASK CLEARANCES AS PER THE REQUIRED" at 51.193,-23.748 h1.52
  text "PCB MUST BEAR THE UL94V-0 UL REGISTERED MATERIAL ID NUMBER" at 193.203,-25.008 h1.52
  text "MANUFACTURING CAPABILITIES," at 51.193,-26.418 h1.52
  text "ADDITIONAL REQUIREMENTS:" at 192.503,-29.311 h1.52
  text "13.100% CONTINUITY TESTING USING DATABASE NETLIST SHALL BE PERFORMED." at 51.193,-31.475 h1.52
  text "MICROSECTION:" at 194.402,-32.032 h1.52
  text "YES" at 217.408,-32.032 h1.52
  text "14.ALL INNER LAYER UNCONNECTED PADS SHALL BE REMOVED." at 51.193,-34.652 h1.52
  text "REQUIRED" at 239.29,-35.698 h1.52
  text "BARE BOARD ELEC. TEST:" at 194.402,-35.771 h1.52
  text "NONE" at 227.568,-35.771 h1.52
  text "X" at 236.293,-35.771 h1.52
  text "PER ORDER" at 254.327,-35.771 h1.52
  text "15.LOCAL FIDUCIALS MUST BE FREE OF ANY MARKINGS." at 51.193,-37.83 h1.52
  text "XX MIL VIAS REQUIRE NON-CONDUCTIVE FILL AND PLANARIZE" at 198.673,-40.976 h1.5
  text "XX MIL VIAS REQUIRE CONDUCTIVE FILL AND PLANARIZE" at 198.876,-43.617 h1.52
  text "16. FILL ALL 6MIL, 8.02MIL VIAS WITH CONDUCTIVE EPOXY PLATED OVER WITH COPPER.  / THE SURFACE SHOULD BE FLAT ON THE TOP SIDE" at 18.455,-43.918 h1.52
  text "OUTER XX MIL TRACES REQUIRE 50 OHM SINGLE-ENDED IMPEDANCE" at 198.851,-47.767 h1.47
  text "17. FILL ALL 6MIL, 8.03MIL VIAS WITH CONDUCTIVE EPOXY PLATED OVER WITH COPPER.  / THE SURFACE SHOULD BE FLAT ON THE BOTTOM SIDE." at 51.015,-49.271 h1.52
  text "LAYER 2 & 3 (INNER LAYERS) XX MIL WIDE, XX MIL SPACE / TRACES REQUIRE 100 OHM DIFFERENTIAL IMPEDANCE" at 198.648,-53.754 h1.52
  text "18. FILL ALL 8.01MIL VIAS WITH CONDUCTIVE EPOXY PLATED OVER WITH COPPER.  / THE SURFACE SHOULD BE FLAT ON BOTH TOP AND BOTTOM SIDE." at 51.015,-54.58 h1.52
  text "19. BOARD DIMENSION: 90 MM X 53.36 MM." at 51.193,-59.223 h1.52
  text "20.TOP,L6,L7 AND BOTTOM COPPER THICKNESS IS 1 OUNCE(PROCESSED THICKNESS) /  AND REMASINLIG LAYERS WILL BE HALF OUNCE" at 51.112,-65.377 h1.52
  text "21. ALL VIAS ARE TENTED EXCEPT ON PAD VIAS" at 51.734,-68.382 h1.52
M11 Gerber Information:
  lines w0.254: -102.784,-100.031 64.856,-100.031 ; -102.784,-94.866 64.907,-94.866 ; -102.784,-89.702 -102.784,-105.196 -1.057,-105.196 64.907,-105.196 64.907,-89.702 -102.771,-89.702 -102.771,-105.196 -62.753,-105.196 ; -40.173,-105.196 -40.173,-89.702 ; -7.991,-94.866 -7.991,-89.702 ; 13.345,-94.866 13.345,-89.702 ; 29.144,-105.361 29.144,-100.209
  text "ALL ARTWORK VIEWED FROM TOP SIDE" at -101.171,-93.059 h1.52
  text "BOARD #:" at -38.268,-93.059 h1.52
  text ".PRJ_Number" at -24.412,-93.059 h1.52
  text "REV:" at -2.962,-93.059 h1.52
  text ".PCB_Rev" at 4.442,-93.059 h1.52
  text "SVN REV:" at 18.324,-93.059 h1.52
  text ".VersionControl_RevNumber" at 31.176,-93.059 h1.52
  text "LAYER NAME =" at -101.171,-98.21 h1.52
  text "TID #:" at -38.268,-98.223 h1.52
  text ".TID" at -24.412,-98.223 h1.52
  text "PLOT NAME =" at -101.171,-103.439 h1.52
  text ".plot_File_Name" at -80.711,-103.439 h1.52
  text "GENERATED    :" at -38.217,-103.439 h1.52
  text ".Print_Date" at -16.132,-103.439 h1.52
  text ".Print_Time" at 2.385,-103.439 h1.52
  text "TEXAS INSTRUMENTS" at 34.503,-103.439 h1.52
M12 Stackup:
  drawing of 503 lines, arcs and shapes, not listed
  text "Layer" at -77.181,94.935 h1.52
  text "Name" at -66.769,94.935 h1.52
  text "Material" at -43.154,94.935 h1.52
  text "Thickness" at -21.316,94.935 h1.52
  text "Constant" at -4.81,94.935 h1.52
  text "Board Layer Stack" at 9.665,94.935 h1.52
  text "Top Overlay" at -66.769,91.887 h1.52
  text "Top Solder" at -66.769,88.839 h1.52
  text "Solder Resist" at -43.154,88.839 h1.52
  text "1.00mil" at -21.316,88.839 h1.52
  text "3.5" at -4.81,88.839 h1.52
  text "1" at -77.181,85.791 h1.52
  text "Top Layer" at -66.769,85.791 h1.52
  text "2.76mil" at -21.316,85.791 h1.52
  text "Dielectric1" at -66.769,82.743 h1.52
  text "FR-4" at -43.154,82.743 h1.52
  text "7.87mil" at -21.316,82.743 h1.52
  text "4.2" at -4.81,82.743 h1.52
  text "2" at -77.181,79.695 h1.52
  text "GND1" at -66.769,79.695 h1.52
  text "CF-004" at -43.154,79.695 h1.52
  text "0.69mil" at -21.316,79.695 h1.52
  text "Dielectric 2" at -66.769,76.647 h1.52
  text "PP-006" at -43.154,76.647 h1.52
  text "7.87mil" at -21.316,76.647 h1.52
  text "4.1" at -4.81,76.647 h1.52
  text "3" at -77.181,73.599 h1.52
  text "Signal 1" at -66.769,73.599 h1.52
  text "CF-004" at -43.154,73.599 h1.52
  text "0.69mil" at -21.316,73.599 h1.52
  text "Dielectric 3" at -66.769,70.551 h1.52
  text "PP-006" at -43.154,70.551 h1.52
  text "7.87mil" at -21.316,70.551 h1.52
  text "4.1" at -4.81,70.551 h1.52
  text "4" at -77.181,67.503 h1.52
  text "Power 1" at -66.769,67.503 h1.52
  text "CF-004" at -43.154,67.503 h1.52
  text "0.69mil" at -21.316,67.503 h1.52
  text "Dielectric 4" at -66.769,64.455 h1.52
  text "PP-006" at -43.154,64.455 h1.52
  text "7.87mil" at -21.316,64.455 h1.52
  text "4.1" at -4.81,64.455 h1.52
  text "5" at -77.181,61.407 h1.52
  text "Power 2" at -66.769,61.407 h1.52
  text "CF-004" at -43.154,61.407 h1.52
  text "0.69mil" at -21.316,61.407 h1.52
  text "Dielectric 5" at -66.769,58.359 h1.52
  text "PP-006" at -43.154,58.359 h1.52
  text "7.87mil" at -21.316,58.359 h1.52
  text "4.1" at -4.81,58.359 h1.52
  text "6" at -77.181,55.311 h1.52
  text "Signal 2" at -66.769,55.311 h1.52
  text "CF-004" at -43.154,55.311 h1.52
  text "0.69mil" at -21.316,55.311 h1.52
  text "Dielectric 6" at -66.769,52.263 h1.52
  text "PP-006" at -43.154,52.263 h1.52
  text "7.87mil" at -21.316,52.263 h1.52
  text "4.1" at -4.81,52.263 h1.52
  text "7" at -77.181,49.215 h1.52
  text "Layer 1" at -66.769,49.215 h1.52
  text "CF-004" at -43.154,49.215 h1.52
  text "0.69mil" at -21.316,49.215 h1.52
  text "Dielectric 1" at -66.769,46.167 h1.52
  text "FR-4" at -43.154,46.167 h1.52
  text "7.87mil" at -21.316,46.167 h1.52
  text "4.1" at -4.81,46.167 h1.52
  text "8" at -77.181,43.119 h1.52
  text "Bottom Layer" at -66.769,43.119 h1.52
  text "2.76mil" at -21.316,43.119 h1.52
  text "Bottom Solder" at -66.769,40.071 h1.52
  text "Solder Resist" at -43.154,40.071 h1.52
  text "1.00mil" at -21.316,40.071 h1.52
  text "3.5" at -4.81,40.071 h1.52
  text "Bottom Overlay" at -66.769,37.023 h1.52
M13 Component Bodies Top:
  text ".Layer_Name" at -80.711,-98.21 h1.52
M14 Component Bodies Bottom:
  text ".Layer_Name" at -80.711,-98.21 h1.52
M15 Courtyards Top:
  text ".Layer_Name" at -80.711,-98.21 h1.52
M16 Courtyards Bottom:
  text ".Layer_Name" at -80.711,-98.21 h1.52
Drill Drawing:
  circle w0.254: c63.276,115.063 r0.421
  circle w0.254: c63.276,115.063 r0.702
  circle w0.254: c63.276,89.802 r0.702
  lines w0.254: 62.575,92.258 63.978,92.258 63.978,93.661 62.575,93.661 62.575,92.258 ; 62.575,96.819 63.978,96.819 63.276,95.415 62.575,96.819 ; 62.575,98.573 63.978,98.573 63.978,99.976 62.575,99.976 62.575,98.573 ; 62.575,103.134 63.978,103.134 63.276,101.731 62.575,103.134 ; 62.575,105.239 62.926,105.239 63.276,104.888 63.627,105.239 63.978,105.239 63.627,105.59 63.978,105.941 63.627,105.941 63.276,106.292 62.926,105.941 62.575,105.941 62.926,105.59 62.575,105.239 ; 62.575,108.046 63.276,108.397 63.978,108.046 63.627,108.748 63.978,109.45 63.276,109.099 62.575,109.45 62.926,108.748 62.575,108.046 ; 62.575,111.906 63.276,111.204 63.978,111.906 63.276,112.607 62.575,111.906 ; 62.575,117.87 62.926,117.87 62.926,117.519 63.627,117.519 63.627,117.87 63.978,117.87 63.978,118.572 63.627,118.572 63.627,118.923 62.926,118.923 62.926,118.572 62.575,118.572 62.575,117.87 ; 62.855,92.538 63.697,92.538 63.697,93.38 62.855,93.38 62.855,92.538 ; 62.855,96.538 63.697,96.538 63.276,95.696 62.855,96.538
  lines w0.305: 61.302,88.152 129.942,88.152 ; 61.302,119.73 129.942,119.73 ; 69.884,84.995 69.884,122.887 ; 78.317,84.995 78.317,122.887 ; 94.486,84.995 94.486,122.887 ; 101.068,84.995 101.068,122.887 ; 110.597,84.995 110.597,122.887 ; 61.302,84.995 129.942,84.995 129.942,122.887 61.302,122.887 61.302,84.995
  text "Symbol" at 63.197,120.677 h1.83
  text "Quantity" at 70.831,120.677 h1.83
  text "Finished Hole Size" at 79.264,120.677 h1.83
  text "Plated" at 95.433,120.677 h1.83
  text "Hole Type" at 102.015,120.677 h1.83
  text "Drill Layer Pair" at 111.544,120.677 h1.83
  text "8" at 70.831,117.519 h1.52
  text "5.91mil (0.150mm)" at 79.264,117.519 h1.52
  text "PTH" at 95.433,117.519 h1.52
  text "Round" at 102.015,117.519 h1.52
  text "Top Layer - Bottom Layer" at 111.544,117.519 h1.52
  text "298" at 70.831,114.362 h1.52
  text "7.87mil (0.200mm)" at 79.264,114.362 h1.52
  text "PTH" at 95.433,114.362 h1.52
  text "Round" at 102.015,114.362 h1.52
  text "Top Layer - Bottom Layer" at 111.544,114.362 h1.52
  text "1" at 70.831,111.204 h1.52
  text "8.27mil (0.210mm)" at 79.264,111.204 h1.52
  text "PTH" at 95.433,111.204 h1.52
  text "Round" at 102.015,111.204 h1.52
  text "Top Layer - Bottom Layer" at 111.544,111.204 h1.52
  text "37" at 70.831,108.046 h1.52
  text "8.66mil (0.220mm)" at 79.264,108.046 h1.52
  text "PTH" at 95.433,108.046 h1.52
  text "Round" at 102.015,108.046 h1.52
  text "Top Layer - Bottom Layer" at 111.544,108.046 h1.52
  text "336" at 70.831,104.888 h1.52
  text "9.84mil (0.250mm)" at 79.264,104.888 h1.52
  text "PTH" at 95.433,104.888 h1.52
  text "Round" at 102.015,104.888 h1.52
  text "Top Layer - Bottom Layer" at 111.544,104.888 h1.52
  text "288" at 70.831,101.731 h1.52
  text "11.81mil (0.300mm)" at 79.264,101.731 h1.52
  text "PTH" at 95.433,101.731 h1.52
  text "Round" at 102.015,101.731 h1.52
  text "Top Layer - Bottom Layer" at 111.544,101.731 h1.52
  text "1" at 70.831,98.573 h1.52
  text "19.69mil (0.500mm)" at 79.264,98.573 h1.52
  text "PTH" at 95.433,98.573 h1.52
  text "Round" at 102.015,98.573 h1.52
  text "Top Layer - Bottom Layer" at 111.544,98.573 h1.52
  text "2" at 70.831,95.415 h1.52
  text "31.50mil (0.800mm)" at 79.264,95.415 h1.52
  text "PTH" at 95.433,95.415 h1.52
  text "Round" at 102.015,95.415 h1.52
  text "Top Layer - Bottom Layer" at 111.544,95.415 h1.52
  text "3" at 70.831,92.258 h1.52
  text "35.43mil (0.900mm)" at 79.264,92.258 h1.52
  text "PTH" at 95.433,92.258 h1.52
  text "Round" at 102.015,92.258 h1.52
  text "Top Layer - Bottom Layer" at 111.544,92.258 h1.52
  text "2" at 70.831,89.1 h1.52
  text "120.00mil (3.048mm)" at 79.264,89.1 h1.52
  text "NPTH" at 95.433,89.1 h1.52
  text "Round" at 102.015,89.1 h1.52
  text "Top Layer - Bottom Layer" at 111.544,89.1 h1.52
  text "976 Total" at 70.831,85.942 h1.52
  text "Tolerance:" at 59.878,63.563 h1.52
  text "For 6 Mil +0/-6 Mil" at 59.324,60.658 h1.52
  text "Drill Drawing2" at -80.711,-98.21 h1.52
M17 Embedded Cavity:
  text ".Layer_Name" at -80.711,-98.21 h1.52
M18 Embedded Assembly:
  text ".Layer_Name" at -80.711,-98.21 h1.52
M19 Embedded Keepout:
  text ".Layer_Name" at -80.711,-98.21 h1.52

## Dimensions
-1.104,2.32 to -20.549,-51.037 on M2 Board Dimensions
-19.279,-48.136 to 7.13,-43.056 on M2 Board Dimensions
-52.232,-43.058 to -2.374,1.05 on M2 Board Dimensions
-95.367,-86.565 to -69.967,-86.565 on M2 Board Dimensions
